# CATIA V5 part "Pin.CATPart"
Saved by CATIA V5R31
Part number: Pin
Bounding box of the stored display mesh (mm): x -10.997 to 10.997, y 0 to 38, z -10.885 to 10.885
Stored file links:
  D:\PROJECTS\Project 2021\US EDITION\CATIA V5 6R 2021\Resources\Part Files\c14_catia_v5_6r2021_prt\c14-catia-v5-6r2021-figr-14-26 & 27\Part & Asm\Pin.CATPart
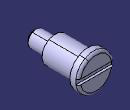
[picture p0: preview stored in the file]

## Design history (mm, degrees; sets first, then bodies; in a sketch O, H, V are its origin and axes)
Body1 (main body)
  Sketch1 on yz-plane, origin (0, 0, 0), H (0, 1, 0), V (0, 0, 1)
    line L1 (0, 0) -> (0, 5)
    line L2 (0, 5) -> (13, 5)
    line L3 (13, 5) -> (13, 8)
    line L4 (13, 8) -> (33, 8)
    line L5 (33, 8) -> (33, 11)
    line L6 (33, 11) -> (38, 11)
    line L7 (38, 11) -> (38, 0)
    point P7 (38, 0)
    line L8 (38, 0) -> (0, 0)
    distance L8 L6 = 11
    distance L4 L8 = 8
    length L8 = 38
    distance L2 L8 = 5
    length L6 = 5
    length L4 = 20
    vertical: L1 V, L3 V, L5 V, L7 V
    horizontal: L2 H, L4 H, L8 H, L6 H
    coincidence: P7 H
  Shaft1: profile Sketch1, axis edge of Sketch1, angle 360
  Chamfer1: length 1.5, angle 45, on 1 edge
  Fillet1: radius 1.5, on 1 edge
  Sketch2 on face of Shaft1, origin (0, 38, 0), H (-1, 0, 0), V (0, 0, 1)
    line L1 (-15.6575, 1.5) -> (20.3727, 1.5)
    line L2 (20.3727, 1.5) -> (20.3727, -1.5)
    line L3 (20.3727, -1.5) -> (-15.6575, -1.5)
    line L4 (-15.6575, -1.5) -> (-15.6575, 1.5)
    distance H L3 = 1.5
    length L4 = 3
    horizontal: L1 H, L3 H
    vertical: L2 V, L4 V
  Pocket1: profile Sketch2, direction (0, -1, 0), length 1.5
